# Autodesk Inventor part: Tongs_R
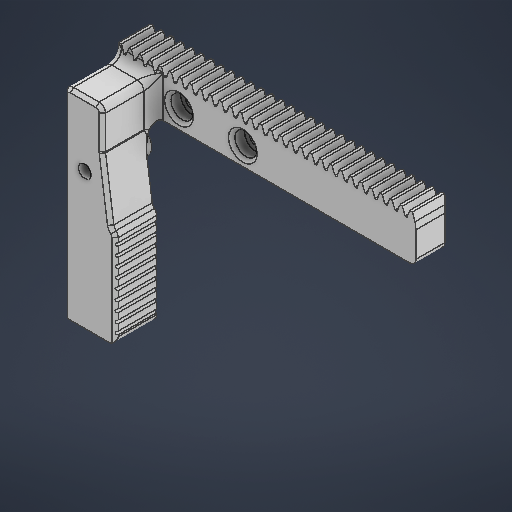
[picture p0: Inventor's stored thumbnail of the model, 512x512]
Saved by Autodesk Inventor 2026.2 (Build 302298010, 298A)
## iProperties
Company: Open CASCADE
Created: 2026-05
Part Number: Tongs_R
Material: 일반
Description: Open CASCADE Model
Document SubType Name: Modeling
Designer: work
Authority: Unknown
Density: 1 g/cm^3
Appearance: 기본값
Sending System: Open CASCADE 7.8
Preprocessor: Open CASCADE STEP processor 7.8
Title: Open CASCADE Shape Model
Author: Author
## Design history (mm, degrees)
feature "기준1"
sketch "스케치1"
  geometry: L1 (0.33, 2)-(1.149, 4.25) reference; L2 (0, 0)-(0.33, 2) reference; L3 (94.248, 0)-(0, 0) reference; L4 (93.917, 2)-(94.248, 0) reference; L5 (93.098, 4.25)-(93.917, 2) reference; L6 (92.256, 4.25)-(93.098, 4.25) reference; L7 (91.437, 2)-(92.256, 4.25) reference; L8 (90.776, 2)-(91.437, 2) reference; L9 (89.957, 4.25)-(90.776, 2) reference; L10 (89.114, 4.25)-(89.957, 4.25) reference; L11 (88.295, 2)-(89.114, 4.25) reference; L12 (87.634, 2)-(88.295, 2) reference; L13 (86.815, 4.25)-(87.634, 2) reference; L14 (85.972, 4.25)-(86.815, 4.25) reference; L15 (85.153, 2)-(85.972, 4.25) reference; L16 (84.493, 2)-(85.153, 2) reference; L17 (83.674, 4.25)-(84.493, 2) reference; L18 (82.831, 4.25)-(83.674, 4.25) reference; L19 (82.012, 2)-(82.831, 4.25) reference; L20 (81.351, 2)-(82.012, 2) reference; L21 (80.532, 4.25)-(81.351, 2) reference; L22 (79.689, 4.25)-(80.532, 4.25) reference; L23 (78.87, 2)-(79.689, 4.25) reference; L24 (78.209, 2)-(78.87, 2) reference; L25 (77.39, 4.25)-(78.209, 2) reference; L26 (76.548, 4.25)-(77.39, 4.25) reference; L27 (75.729, 2)-(76.548, 4.25) reference; L28 (75.068, 2)-(75.729, 2) reference; L29 (74.249, 4.25)-(75.068, 2) reference; L30 (73.406, 4.25)-(74.249, 4.25) reference; L31 (72.587, 2)-(73.406, 4.25) reference; L32 (71.926, 2)-(72.587, 2) reference; L33 (71.107, 4.25)-(71.926, 2) reference; L34 (70.264, 4.25)-(71.107, 4.25) reference; L35 (69.445, 2)-(70.264, 4.25) reference; L36 (68.785, 2)-(69.445, 2) reference; L37 (67.966, 4.25)-(68.785, 2) reference; L38 (67.123, 4.25)-(67.966, 4.25) reference; L39 (66.304, 2)-(67.123, 4.25) reference; L40 (65.643, 2)-(66.304, 2) reference; L41 (64.824, 4.25)-(65.643, 2) reference; L42 (63.981, 4.25)-(64.824, 4.25) reference; L43 (63.162, 2)-(63.981, 4.25) reference; L44 (62.501, 2)-(63.162, 2) reference; L45 (61.682, 4.25)-(62.501, 2) reference; L46 (60.84, 4.25)-(61.682, 4.25) reference; L47 (60.021, 2)-(60.84, 4.25) reference; L48 (59.36, 2)-(60.021, 2) reference; L49 (58.541, 4.25)-(59.36, 2) reference; L50 (57.698, 4.25)-(58.541, 4.25) reference; L51 (56.879, 2)-(57.698, 4.25) reference; L52 (56.218, 2)-(56.879, 2) reference; L53 (55.399, 4.25)-(56.218, 2) reference; L54 (54.556, 4.25)-(55.399, 4.25) reference; L55 (53.738, 2)-(54.556, 4.25) reference; L56 (53.077, 2)-(53.738, 2) reference; L57 (52.258, 4.25)-(53.077, 2) reference; L58 (51.415, 4.25)-(52.258, 4.25) reference; L59 (50.596, 2)-(51.415, 4.25) reference; L60 (49.935, 2)-(50.596, 2) reference; L61 (49.116, 4.25)-(49.935, 2) reference; L62 (48.273, 4.25)-(49.116, 4.25) reference; L63 (47.454, 2)-(48.273, 4.25) reference; L64 (46.793, 2)-(47.454, 2) reference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; 1 further point
  constraints: 8 end point, 2 parallel, 1 horizontal, 1 perpendicular, 1 point on line
  dimensions: "d0" = 10 distance of L123.end L124.end
extrude "돌출1" join sketch "스케치1" stored distance "d1" = 10; taper "d2" = 0 deg
sketch "스케치2"
  geometry: L1 (0.33, 12)-(1.149, 14.25) reference; L2 (0, 10)-(0.33, 12) reference; L3 (0, 10)-(0, 0) reference; L4 (0, 0)-(94.248, 0) reference; L5 (94.248, 0)-(94.248, 10) reference; L6 (93.917, 12)-(94.248, 10) reference; L7 (93.098, 14.25)-(93.917, 12) reference; L8 (92.256, 14.25)-(93.098, 14.25) reference; L9 (91.437, 12)-(92.256, 14.25) reference; L10 (90.776, 12)-(91.437, 12) reference; L11 (89.957, 14.25)-(90.776, 12) reference; L12 (89.114, 14.25)-(89.957, 14.25) reference; L13 (88.295, 12)-(89.114, 14.25) reference; L14 (87.634, 12)-(88.295, 12) reference; L15 (86.815, 14.25)-(87.634, 12) reference; L16 (85.972, 14.25)-(86.815, 14.25) reference; L17 (85.153, 12)-(85.972, 14.25) reference; L18 (84.493, 12)-(85.153, 12) reference; L19 (83.674, 14.25)-(84.493, 12) reference; L20 (82.831, 14.25)-(83.674, 14.25) reference; L21 (82.012, 12)-(82.831, 14.25) reference; L22 (81.351, 12)-(82.012, 12) reference; L23 (80.532, 14.25)-(81.351, 12) reference; L24 (79.689, 14.25)-(80.532, 14.25) reference; L25 (78.87, 12)-(79.689, 14.25) reference; L26 (78.209, 12)-(78.87, 12) reference; L27 (77.39, 14.25)-(78.209, 12) reference; L28 (76.548, 14.25)-(77.39, 14.25) reference; L29 (75.729, 12)-(76.548, 14.25) reference; L30 (75.068, 12)-(75.729, 12) reference; L31 (74.249, 14.25)-(75.068, 12) reference; L32 (73.406, 14.25)-(74.249, 14.25) reference; L33 (72.587, 12)-(73.406, 14.25) reference; L34 (71.926, 12)-(72.587, 12) reference; L35 (71.107, 14.25)-(71.926, 12) reference; L36 (70.264, 14.25)-(71.107, 14.25) reference; L37 (69.445, 12)-(70.264, 14.25) reference; L38 (68.785, 12)-(69.445, 12) reference; L39 (67.966, 14.25)-(68.785, 12) reference; L40 (67.123, 14.25)-(67.966, 14.25) reference; L41 (66.304, 12)-(67.123, 14.25) reference; L42 (65.643, 12)-(66.304, 12) reference; L43 (64.824, 14.25)-(65.643, 12) reference; L44 (63.981, 14.25)-(64.824, 14.25) reference; L45 (63.162, 12)-(63.981, 14.25) reference; L46 (62.501, 12)-(63.162, 12) reference; L47 (61.682, 14.25)-(62.501, 12) reference; L48 (60.84, 14.25)-(61.682, 14.25) reference; L49 (60.021, 12)-(60.84, 14.25) reference; L50 (59.36, 12)-(60.021, 12) reference; L51 (58.541, 14.25)-(59.36, 12) reference; L52 (57.698, 14.25)-(58.541, 14.25) reference; L53 (56.879, 12)-(57.698, 14.25) reference; L54 (56.218, 12)-(56.879, 12) reference; L55 (55.399, 14.25)-(56.218, 12) reference; L56 (54.556, 14.25)-(55.399, 14.25) reference; L57 (53.738, 12)-(54.556, 14.25) reference; L58 (53.077, 12)-(53.738, 12) reference; L59 (52.258, 14.25)-(53.077, 12) reference; L60 (51.415, 14.25)-(52.258, 14.25) reference; L61 (50.596, 12)-(51.415, 14.25) reference; L62 (49.935, 12)-(50.596, 12) reference; L63 (49.116, 14.25)-(49.935, 12) reference; L64 (48.273, 14.25)-(49.116, 14.25) reference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; C1 r 2 at (40, 5.688); C2 r 2 at (20, 5.688); 3 further points
  constraints: 8 end point, 5 point on line, 4 perpendicular, 2 centre point, 2 midpoint, 1 horizontal
  dimensions: "d4" = 0.5625 distance of L126.end point (47.124, 13.688); "d5" = 8 distance of point (47.124, 5.688) point (47.124, 13.688); "d6" = 4 diameter of C1; "d7" = 4 diameter of C2; "d8" = 20 distance of C1.centre C2.centre; "d60" = 20 distance of L128.start C2.centre
extrude "돌출2" cut sketch "스케치2" extent not by distance; stored distance "d10" = 0; taper "d11" = 0 deg
sketch "스케치5"
  geometry: L1 (0, 10)-(12, 10); L2 (12, 10)-(12, -52.624); L3 (12, -52.624)-(0, -52.624); L4 (12, -52.624)-(16, -52.624); L5 (16, -22.624)-(12, -22.624); L6 (12, -22.624)-(12, -52.624); L7 (0, -49.624)-(16, -49.624); C1 r 0.5 at (16, -49.624); C2 r 0.5 at (0, -49.624); C3 r 0.5 at (16, -46.624); C4 r 0.5 at (0, -46.624); C5 r 0.5 at (16, -43.624); C6 r 0.5 at (0, -43.624); C7 r 0.5 at (16, -40.624); C8 r 0.5 at (0, -40.624); C9 r 0.5 at (16, -37.624); C10 r 0.5 at (0, -37.624); C11 r 0.5 at (16, -34.624); C12 r 0.5 at (0, -34.624); C13 r 0.5 at (16, -31.624); C14 r 0.5 at (0, -31.624); C15 r 0.5 at (16, -28.624); C16 r 0.5 at (0, -28.624); C17 r 0.5 at (16, -25.624); C18 r 0.5 at (0, -25.624); 39 further points
  constraints: 18 centre point, 14 end point, 4 horizontal, 3 vertical, 2 parallel, 1 coincident, 1 perpendicular, 40 other
  dimensions: "d36" = 62.624 distance of L1.end L2.end; "d37" = 12 distance of L2.end L3.end; "d38" = 30 distance of L5.start L4.end; "d39" = 4 distance of L2.end L4.end; "d40" = 1 diameter of C1; "d41" = 1 diameter of C2; "d42" = 3 distance between parallel lines of L3 L7; "d45" = 3 distance of L7.end C3.centre
extrude "돌출5" join sketch "스케치5" distance "d50" = 16; taper "d51" = 0 deg
chamfer "모따기2" distance "d52" = 20; stored, may be unused: second distance "d53" = 2, angle "d54" = 171.887 deg
sketch "스케치6"
  geometry: L1 (0, -52.624)-(-16, -52.624) reference; L2 (-3, -52.624)-(-3, -10); L3 (10, 10)-(10, 0) reference; L4 (0, 0)-(10, 0) reference; L5 (0, 0)-(0, -25.124) reference; L6 (0, -25.124)-(-16, -25.124) reference; L7 (-16, 10)-(-16, -25.124) reference; L8 (0, 10)-(-16, 10) reference; L9 (10, 10)-(0, 10) reference; L10 (0, -26.124)-(0, -25.124) reference; L11 (-3, -52.624)-(0, -52.624); L12 (0, -52.624)-(0, -25.124); L13 (0, -25.124)-(-3, -25.124); L14 (-3, -25.124)-(-3, -52.624); A1 r 18.167 centre (15.167, -10) between (0, 0) and (-3, -10); 3 further points
  constraints: 10 end point, 2 parallel, 2 point on circle, 1 centre point, 1 horizontal, 1 perpendicular, 1 point on line, 1 tangent, 1 vertical
  dimensions: "d55" = 10 vertical distance of L4.start L2.end; "d56" = 3 horizontal distance of L4.start L2.end
extrude "돌출6" cut sketch "스케치6" extent not by distance; stored distance "d57" = 0; taper "d58" = 0 deg
fillet "모깎기2" dims "d59" = 3
fillet "모깎기3" dims "d61" = 2
fillet "모깎기4" dims "d62" = 2
chamfer "모따기3" distance "d63" = 1; stored, may be unused: second distance "d64" = 2, angle "d65" = 171.887 deg
sketch "스케치7"
  geometry: L1 (79.248, 2)-(79.248, 10) reference; L2 (78.917, 12)-(79.248, 10) reference; L3 (78.098, 14.25)-(78.917, 12) reference; L4 (77.256, 14.25)-(78.098, 14.25) reference; L5 (76.437, 12)-(77.256, 14.25) reference; L6 (75.776, 12)-(76.437, 12) reference; L7 (74.957, 14.25)-(75.776, 12) reference; L8 (74.114, 14.25)-(74.957, 14.25) reference; L9 (73.295, 12)-(74.114, 14.25) reference; L10 (72.634, 12)-(73.295, 12) reference; L11 (71.815, 14.25)-(72.634, 12) reference; L12 (70.972, 14.25)-(71.815, 14.25) reference; L13 (70.153, 12)-(70.972, 14.25) reference; L14 (69.493, 12)-(70.153, 12) reference; L15 (68.674, 14.25)-(69.493, 12) reference; L16 (67.831, 14.25)-(68.674, 14.25) reference; L17 (67.012, 12)-(67.831, 14.25) reference; L18 (66.351, 12)-(67.012, 12) reference; L19 (65.532, 14.25)-(66.351, 12) reference; L20 (64.689, 14.25)-(65.532, 14.25) reference; L21 (63.87, 12)-(64.689, 14.25) reference; L22 (63.209, 12)-(63.87, 12) reference; L23 (62.39, 14.25)-(63.209, 12) reference; L24 (61.548, 14.25)-(62.39, 14.25) reference; L25 (60.729, 12)-(61.548, 14.25) reference; L26 (60.068, 12)-(60.729, 12) reference; L27 (59.249, 14.25)-(60.068, 12) reference; L28 (58.406, 14.25)-(59.249, 14.25) reference; L29 (57.587, 12)-(58.406, 14.25) reference; L30 (56.926, 12)-(57.587, 12) reference; L31 (56.107, 14.25)-(56.926, 12) reference; L32 (55.264, 14.25)-(56.107, 14.25) reference; L33 (54.445, 12)-(55.264, 14.25) reference; L34 (53.785, 12)-(54.445, 12) reference; L35 (52.966, 14.25)-(53.785, 12) reference; L36 (52.123, 14.25)-(52.966, 14.25) reference; L37 (51.304, 12)-(52.123, 14.25) reference; L38 (50.643, 12)-(51.304, 12) reference; L39 (49.824, 14.25)-(50.643, 12) reference; L40 (48.981, 14.25)-(49.824, 14.25) reference; L41 (48.162, 12)-(48.981, 14.25) reference; L42 (47.501, 12)-(48.162, 12) reference; L43 (46.682, 14.25)-(47.501, 12) reference; L44 (45.84, 14.25)-(46.682, 14.25) reference; L45 (45.021, 12)-(45.84, 14.25) reference; L46 (44.36, 12)-(45.021, 12) reference; L47 (43.541, 14.25)-(44.36, 12) reference; L48 (42.698, 14.25)-(43.541, 14.25) reference; L49 (41.879, 12)-(42.698, 14.25) reference; L50 (41.218, 12)-(41.879, 12) reference; L51 (40.399, 14.25)-(41.218, 12) reference; L52 (39.556, 14.25)-(40.399, 14.25) reference; L53 (38.738, 12)-(39.556, 14.25) reference; L54 (38.077, 12)-(38.738, 12) reference; L55 (37.258, 14.25)-(38.077, 12) reference; L56 (36.415, 14.25)-(37.258, 14.25) reference; L57 (35.596, 12)-(36.415, 14.25) reference; L58 (34.935, 12)-(35.596, 12) reference; L59 (34.116, 14.25)-(34.935, 12) reference; L60 (33.273, 14.25)-(34.116, 14.25) reference; L61 (32.454, 12)-(33.273, 14.25) reference; L62 (31.793, 12)-(32.454, 12) reference; L63 (30.975, 14.25)-(31.793, 12) reference; L64 (30.132, 14.25)-(30.975, 14.25) reference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; C1 r 2 at (25, 5.688) reference; C2 r 2 at (5, 5.688) reference; A1 r 2 centre (77.248, 2) between (77.248, 0) and (79.248, 2) reference; 3 further points
  constraints: 2 coincident
hole "구멍1" sketch "스케치7" at (5, 5.688), (25, 5.688) diameter "d66" = 4; stored, may be unused: countersink angle "d70" = 90 deg, drill point angle "d72" = 118 deg; dims "d67" = 6, "d68" = 7, "d69" = 4, "d71" = 3 (= d59)
chamfer "모따기4" distance "d73" = 1; stored, may be unused: second distance "d74" = 2, angle "d75" = 171.887 deg
sketch "스케치8"
  geometry: L1 (13.051, -40.124)-(13.051, -40.624) reference; L2 (13.051, -37.124)-(13.051, -39.124) reference; L3 (13.051, -34.124)-(13.051, -36.124) reference; L4 (13.051, -31.124)-(13.051, -33.124) reference; L5 (13.051, -28.124)-(13.051, -30.124) reference; L6 (13.051, -25.124)-(13.051, -27.124) reference; L7 (13.051, -22.124)-(13.051, -24.124) reference; L8 (13.051, -19.124)-(13.051, -21.124) reference; L9 (13.051, -16.124)-(13.051, -18.124) reference; L10 (13.051, 0)-(13.051, -15.124) reference; L11 (13.051, 0)-(0, 0) reference; L12 (-1.568, -10.998)-(0, 0) reference; L13 (-2.949, -15.124)-(-2.949, -13.756) reference; L14 (-2.949, -18.124)-(-2.949, -16.124) reference; L15 (-2.949, -21.124)-(-2.949, -19.124) reference; L16 (-2.949, -24.124)-(-2.949, -22.124) reference; L17 (-2.949, -27.124)-(-2.949, -25.124) reference; L18 (-2.949, -30.124)-(-2.949, -28.124) reference; L19 (-2.949, -33.124)-(-2.949, -31.124) reference; L20 (-2.949, -36.124)-(-2.949, -34.124) reference; L21 (-2.949, -39.124)-(-2.949, -37.124) reference; L22 (-2.949, -40.624)-(-2.949, -40.124) reference; L23 (11.051, -42.624)-(-0.949, -42.624) reference; C1 r 4 at (6.526, 0); A1 r 2 centre (11.051, -40.624) between (11.051, -42.624) and (13.051, -40.624) reference; A2 r 0.5 centre (13.051, -39.624) between (13.051, -39.124) and (13.051, -40.124) reference; A3 r 0.5 centre (13.051, -36.624) between (13.051, -36.124) and (13.051, -37.124) reference; A4 r 0.5 centre (13.051, -33.624) between (13.051, -33.124) and (13.051, -34.124) reference; A5 r 0.5 centre (13.051, -30.624) between (13.051, -30.124) and (13.051, -31.124) reference; A6 r 0.5 centre (13.051, -27.624) between (13.051, -27.124) and (13.051, -28.124) reference; A7 r 0.5 centre (13.051, -24.624) between (13.051, -24.124) and (13.051, -25.124) reference; A8 r 0.5 centre (13.051, -21.624) between (13.051, -21.124) and (13.051, -22.124) reference; A9 r 0.5 centre (13.051, -18.624) between (13.051, -18.124) and (13.051, -19.124) reference; A10 r 0.5 centre (13.051, -15.624) between (13.051, -15.124) and (13.051, -16.124) reference; A11 r 2 centre (-3.548, -10.716) between (-2.248, -12.236) and (-1.568, -10.998) reference; A12 r 2 centre (-0.949, -13.756) between (-2.248, -12.236) and (-2.949, -13.756) reference; A13 r 0.5 centre (-2.949, -15.624) between (-2.949, -16.124) and (-2.949, -15.124) reference; A14 r 0.5 centre (-2.949, -18.624) between (-2.949, -19.124) and (-2.949, -18.124) reference; A15 r 0.5 centre (-2.949, -21.624) between (-2.949, -22.124) and (-2.949, -21.124) reference; A16 r 0.5 centre (-2.949, -24.624) between (-2.949, -25.124) and (-2.949, -24.124) reference; A17 r 0.5 centre (-2.949, -27.624) between (-2.949, -28.124) and (-2.949, -27.124) reference; A18 r 0.5 centre (-2.949, -30.624) between (-2.949, -31.124) and (-2.949, -30.124) reference; A19 r 0.5 centre (-2.949, -33.624) between (-2.949, -34.124) and (-2.949, -33.124) reference; A20 r 0.5 centre (-2.949, -36.624) between (-2.949, -37.124) and (-2.949, -36.124) reference; A21 r 0.5 centre (-2.949, -39.624) between (-2.949, -40.124) and (-2.949, -39.124) reference; A22 r 2 centre (-0.949, -40.624) between (-2.949, -40.624) and (-0.949, -42.624) reference; 1 further point
  constraints: 1 centre point, 1 midpoint
  dimensions: "d76" = 8 diameter of C1
extrude "돌출7" join sketch "스케치8" distance "d77" = 4; taper "d78" = 0 deg
fillet "모깎기5" dims "d79" = 2
sketch "스케치9"
  geometry: C1 r 2 at (0, 0); C2 r 4 at (0, 0) reference; 1 further point
  constraints: 1 centre point, 1 concentric
  dimensions: "d80" = 4 diameter of C1
extrude "돌출8" cut sketch "스케치9" extent not by distance; stored distance "d81" = 0; taper "d82" = 0 deg
node "솔리드1"
node "투영된 루프1"
node "투영된 루프2"
node "스케치 - 직사각형 패턴2" dims "d45" = 3, "d48" = 10
node "투영된 루프5"
node "투영된 루프6"
node "투영된 루프7"
feature "A9D066F2-1C7D-4E18-AEED-F7BC21143FA4" dims "d66" = 4, "d67" = 6, "d68" = 7, "d69" = 4, "d70" = 90 deg, "d71" = 3 (= d59), "d72" = 118 deg
